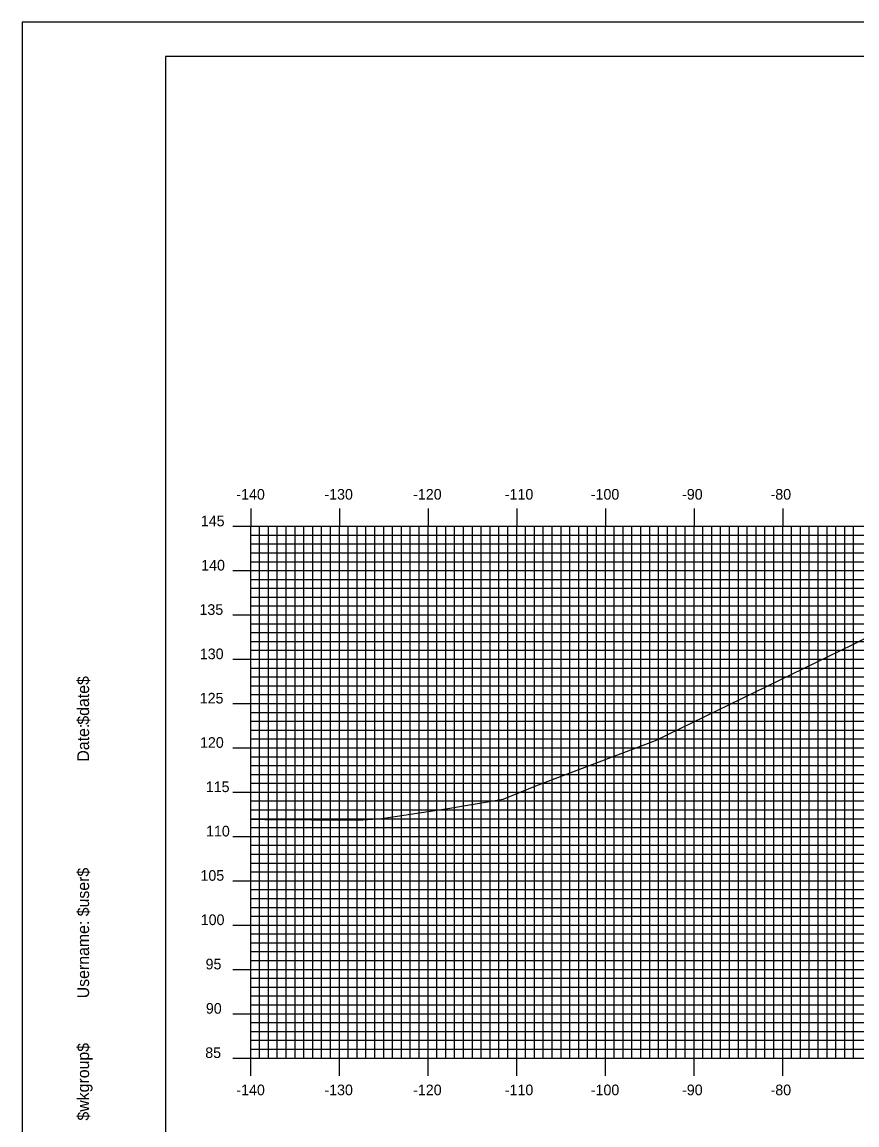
# Model space of a CAD drawing. Extents: x 859865 to 860208, y 364765 to 364985.
# Drawn here: x 859864.6 to 859958.8, y 364860.7 to 364985.2 of the extents above; entities that cross this region are included whole.
import ezdxf

# ---------------------------------------------------------------- set-up
doc = ezdxf.new("R2010")
doc.units = 0
for name, color, linetype in [('BORDER', 7, 'Continuous'), ('H_V ANNOTATION', 7, 'Continuous'), ('MAJOR', 7, 'Continuous'), ('MINOR', 7, 'Continuous'), ('PLOT BOUNDARY', 7, 'Continuous'), ('S_Roadway_Centerline', 7, 'Continuous')]:
    doc.layers.add(name, color=color, linetype=linetype)

msp = doc.modelspace()

# ---------------------------------------------------------------- linework, layer by layer
at = {"layer": 'BORDER'}
msp.add_lwpolyline([(859880.79, 364771.3), (860200.79, 364771.3), (860200.79, 364981.3), (859880.79, 364981.3)], close=True, dxfattribs=at)
at = {"layer": 'MAJOR'}
for p, q in [((859890.39, 364930.31), (859890.39, 364928.3)), ((859900.39, 364930.31), (859900.39, 364928.3)), ((859910.39, 364930.31), (859910.39, 364928.3)), ((859920.39, 364930.31), (859920.39, 364928.3)), ((859930.39, 364930.31), (859930.39, 364928.3)), ((859940.39, 364930.31), (859940.39, 364928.3)), ((859950.39, 364930.31), (859950.39, 364928.3)), ((859888.38, 364928.3), (859890.39, 364928.3)), ((859890.39, 364928.3), (860170.39, 364928.3)), ((859890.39, 364868.3), (859890.39, 364928.3)), ((859890.39, 364868.3), (859890.39, 364928.3)), ((859890.39, 364928.3), (860170.39, 364928.3)), ((859900.39, 364868.3), (859900.39, 364928.3)), ((859910.39, 364868.3), (859910.39, 364928.3)), ((859920.39, 364868.3), (859920.39, 364928.3)), ((859930.39, 364868.3), (859930.39, 364928.3)), ((859940.39, 364868.3), (859940.39, 364928.3)), ((859950.39, 364868.3), (859950.39, 364928.3)), ((859888.38, 364923.3), (859890.39, 364923.3)), ((859890.39, 364923.3), (860170.39, 364923.3)), ((859888.38, 364918.3), (859890.39, 364918.3)), ((859890.39, 364918.3), (860170.39, 364918.3)), ((859888.38, 364913.3), (859890.39, 364913.3)), ((859890.39, 364913.3), (860170.39, 364913.3)), ((859888.38, 364908.3), (859890.39, 364908.3)), ((859890.39, 364908.3), (860170.39, 364908.3)), ((859888.38, 364903.3), (859890.39, 364903.3)), ((859890.39, 364903.3), (860170.39, 364903.3)), ((859888.38, 364898.3), (859890.39, 364898.3)), ((859890.39, 364898.3), (860170.39, 364898.3)), ((859888.38, 364893.3), (859890.39, 364893.3)), ((859890.39, 364893.3), (860170.39, 364893.3)), ((859888.38, 364888.3), (859890.39, 364888.3)), ((859890.39, 364888.3), (860170.39, 364888.3)), ((859888.38, 364883.3), (859890.39, 364883.3)), ((859890.39, 364883.3), (860170.39, 364883.3)), ((859888.38, 364878.3), (859890.39, 364878.3)), ((859890.39, 364878.3), (860170.39, 364878.3)), ((859888.38, 364873.3), (859890.39, 364873.3)), ((859890.39, 364873.3), (860170.39, 364873.3)), ((859888.38, 364868.3), (859890.39, 364868.3)), ((859890.39, 364868.3), (860170.39, 364868.3)), ((859890.39, 364868.3), (860170.39, 364868.3)), ((859890.39, 364866.3), (859890.39, 364868.3)), ((859900.39, 364866.3), (859900.39, 364868.3)), ((859910.39, 364866.3), (859910.39, 364868.3)), ((859920.39, 364866.3), (859920.39, 364868.3)), ((859930.39, 364866.3), (859930.39, 364868.3)), ((859940.39, 364866.3), (859940.39, 364868.3)), ((859950.39, 364866.3), (859950.39, 364868.3))]:
    msp.add_line(p, q, dxfattribs=at)
at = {"layer": 'MINOR'}
for p, q in [((859891.39, 364868.3), (859891.39, 364928.3)), ((859892.39, 364868.3), (859892.39, 364928.3)), ((859893.39, 364868.3), (859893.39, 364928.3)), ((859894.39, 364868.3), (859894.39, 364928.3)), ((859895.39, 364868.3), (859895.39, 364928.3)), ((859896.39, 364868.3), (859896.39, 364928.3)), ((859897.39, 364868.3), (859897.39, 364928.3)), ((859898.39, 364868.3), (859898.39, 364928.3)), ((859899.39, 364868.3), (859899.39, 364928.3)), ((859901.39, 364868.3), (859901.39, 364928.3)), ((859902.39, 364868.3), (859902.39, 364928.3)), ((859903.39, 364868.3), (859903.39, 364928.3)), ((859904.39, 364868.3), (859904.39, 364928.3)), ((859905.39, 364868.3), (859905.39, 364928.3)), ((859906.39, 364868.3), (859906.39, 364928.3)), ((859907.39, 364868.3), (859907.39, 364928.3)), ((859908.39, 364868.3), (859908.39, 364928.3)), ((859909.39, 364868.3), (859909.39, 364928.3)), ((859911.39, 364868.3), (859911.39, 364928.3)), ((859912.39, 364868.3), (859912.39, 364928.3)), ((859913.39, 364868.3), (859913.39, 364928.3)), ((859914.39, 364868.3), (859914.39, 364928.3)), ((859915.39, 364868.3), (859915.39, 364928.3)), ((859916.39, 364868.3), (859916.39, 364928.3)), ((859917.39, 364868.3), (859917.39, 364928.3)), ((859918.39, 364868.3), (859918.39, 364928.3)), ((859919.39, 364868.3), (859919.39, 364928.3)), ((859921.39, 364868.3), (859921.39, 364928.3)), ((859922.39, 364868.3), (859922.39, 364928.3)), ((859923.39, 364868.3), (859923.39, 364928.3)), ((859924.39, 364868.3), (859924.39, 364928.3)), ((859925.39, 364868.3), (859925.39, 364928.3)), ((859926.39, 364868.3), (859926.39, 364928.3)), ((859927.39, 364868.3), (859927.39, 364928.3)), ((859928.39, 364868.3), (859928.39, 364928.3)), ((859929.39, 364868.3), (859929.39, 364928.3)), ((859931.39, 364868.3), (859931.39, 364928.3)), ((859932.39, 364868.3), (859932.39, 364928.3)), ((859933.39, 364868.3), (859933.39, 364928.3)), ((859934.39, 364868.3), (859934.39, 364928.3)), ((859935.39, 364868.3), (859935.39, 364928.3)), ((859936.39, 364868.3), (859936.39, 364928.3)), ((859937.39, 364868.3), (859937.39, 364928.3)), ((859938.39, 364868.3), (859938.39, 364928.3)), ((859939.39, 364868.3), (859939.39, 364928.3)), ((859941.39, 364868.3), (859941.39, 364928.3)), ((859942.39, 364868.3), (859942.39, 364928.3)), ((859943.39, 364868.3), (859943.39, 364928.3)), ((859944.39, 364868.3), (859944.39, 364928.3)), ((859945.39, 364868.3), (859945.39, 364928.3)), ((859946.39, 364868.3), (859946.39, 364928.3)), ((859947.39, 364868.3), (859947.39, 364928.3)), ((859948.39, 364868.3), (859948.39, 364928.3)), ((859949.39, 364868.3), (859949.39, 364928.3)), ((859951.39, 364868.3), (859951.39, 364928.3)), ((859952.39, 364868.3), (859952.39, 364928.3)), ((859953.39, 364868.3), (859953.39, 364928.3)), ((859954.39, 364868.3), (859954.39, 364928.3)), ((859955.39, 364868.3), (859955.39, 364928.3)), ((859956.39, 364868.3), (859956.39, 364928.3)), ((859957.39, 364868.3), (859957.39, 364928.3)), ((859958.39, 364868.3), (859958.39, 364928.3)), ((859890.39, 364927.3), (860170.39, 364927.3)), ((859890.39, 364927.3), (859892.39, 364927.3)), ((859890.39, 364926.3), (860170.39, 364926.3)), ((859890.39, 364926.3), (859892.39, 364926.3)), ((859890.39, 364925.3), (860170.39, 364925.3)), ((859890.39, 364925.3), (859892.39, 364925.3)), ((859890.39, 364924.3), (860170.39, 364924.3)), ((859890.39, 364924.3), (859892.39, 364924.3)), ((859890.39, 364922.3), (860170.39, 364922.3)), ((859890.39, 364922.3), (859892.39, 364922.3)), ((859890.39, 364921.3), (860170.39, 364921.3)), ((859890.39, 364921.3), (859892.39, 364921.3)), ((859890.39, 364920.3), (860170.39, 364920.3)), ((859890.39, 364920.3), (859892.39, 364920.3)), ((859890.39, 364919.3), (860170.39, 364919.3)), ((859890.39, 364919.3), (859892.39, 364919.3)), ((859890.39, 364917.3), (860170.39, 364917.3)), ((859890.39, 364917.3), (859892.39, 364917.3)), ((859890.39, 364916.3), (860170.39, 364916.3)), ((859890.39, 364916.3), (859892.39, 364916.3)), ((859890.39, 364915.3), (860170.39, 364915.3)), ((859890.39, 364915.3), (859892.39, 364915.3)), ((859890.39, 364914.3), (860170.39, 364914.3)), ((859890.39, 364914.3), (859892.39, 364914.3)), ((859890.39, 364912.3), (860170.39, 364912.3)), ((859890.39, 364912.3), (859892.39, 364912.3)), ((859890.39, 364911.3), (860170.39, 364911.3)), ((859890.39, 364911.3), (859892.39, 364911.3)), ((859890.39, 364910.3), (860170.39, 364910.3)), ((859890.39, 364910.3), (859892.39, 364910.3)), ((859890.39, 364909.3), (860170.39, 364909.3)), ((859890.39, 364909.3), (859892.39, 364909.3)), ((859890.39, 364907.3), (860170.39, 364907.3)), ((859890.39, 364907.3), (859892.39, 364907.3)), ((859890.39, 364906.3), (860170.39, 364906.3)), ((859890.39, 364906.3), (859892.39, 364906.3)), ((859890.39, 364905.3), (860170.39, 364905.3)), ((859890.39, 364905.3), (859892.39, 364905.3)), ((859890.39, 364904.3), (860170.39, 364904.3)), ((859890.39, 364904.3), (859892.39, 364904.3)), ((859890.39, 364902.3), (860170.39, 364902.3)), ((859890.39, 364902.3), (859892.39, 364902.3)), ((859890.39, 364901.3), (860170.39, 364901.3)), ((859890.39, 364901.3), (859892.39, 364901.3)), ((859890.39, 364900.3), (860170.39, 364900.3)), ((859890.39, 364900.3), (859892.39, 364900.3)), ((859890.39, 364899.3), (860170.39, 364899.3)), ((859890.39, 364899.3), (859892.39, 364899.3)), ((859890.39, 364897.3), (860170.39, 364897.3)), ((859890.39, 364897.3), (859892.39, 364897.3)), ((859890.39, 364896.3), (860170.39, 364896.3)), ((859890.39, 364896.3), (859892.39, 364896.3)), ((859890.39, 364895.3), (860170.39, 364895.3)), ((859890.39, 364895.3), (859892.39, 364895.3)), ((859890.39, 364894.3), (860170.39, 364894.3)), ((859890.39, 364894.3), (859892.39, 364894.3)), ((859890.39, 364892.3), (860170.39, 364892.3)), ((859890.39, 364892.3), (859892.39, 364892.3)), ((859890.39, 364891.3), (860170.39, 364891.3)), ((859890.39, 364891.3), (859892.39, 364891.3)), ((859890.39, 364890.3), (860170.39, 364890.3)), ((859890.39, 364890.3), (859892.39, 364890.3)), ((859890.39, 364889.3), (860170.39, 364889.3)), ((859890.39, 364889.3), (859892.39, 364889.3)), ((859890.39, 364887.3), (860170.39, 364887.3)), ((859890.39, 364887.3), (859892.39, 364887.3)), ((859890.39, 364886.3), (860170.39, 364886.3)), ((859890.39, 364886.3), (859892.39, 364886.3)), ((859890.39, 364885.3), (860170.39, 364885.3)), ((859890.39, 364885.3), (859892.39, 364885.3)), ((859890.39, 364884.3), (860170.39, 364884.3)), ((859890.39, 364884.3), (859892.39, 364884.3)), ((859890.39, 364882.3), (860170.39, 364882.3)), ((859890.39, 364882.3), (859892.39, 364882.3)), ((859890.39, 364881.3), (860170.39, 364881.3)), ((859890.39, 364881.3), (859892.39, 364881.3)), ((859890.39, 364880.3), (860170.39, 364880.3)), ((859890.39, 364880.3), (859892.39, 364880.3)), ((859890.39, 364879.3), (860170.39, 364879.3)), ((859890.39, 364879.3), (859892.39, 364879.3)), ((859890.39, 364877.3), (860170.39, 364877.3)), ((859890.39, 364877.3), (859892.39, 364877.3)), ((859890.39, 364876.3), (860170.39, 364876.3)), ((859890.39, 364876.3), (859892.39, 364876.3)), ((859890.39, 364875.3), (860170.39, 364875.3)), ((859890.39, 364875.3), (859892.39, 364875.3)), ((859890.39, 364874.3), (860170.39, 364874.3)), ((859890.39, 364874.3), (859892.39, 364874.3)), ((859890.39, 364872.3), (860170.39, 364872.3)), ((859890.39, 364872.3), (859892.39, 364872.3)), ((859890.39, 364871.3), (860170.39, 364871.3)), ((859890.39, 364871.3), (859892.39, 364871.3)), ((859890.39, 364870.3), (860170.39, 364870.3)), ((859890.39, 364870.3), (859892.39, 364870.3)), ((859890.39, 364869.3), (860170.39, 364869.3)), ((859890.39, 364869.3), (859892.39, 364869.3))]:
    msp.add_line(p, q, dxfattribs=at)
at = {"layer": 'PLOT BOUNDARY'}
msp.add_lwpolyline([(859864.6, 364765.18), (860204.6, 364765.18), (860204.6, 364985.18), (859864.6, 364985.18)], close=True, dxfattribs=at)
at = {"layer": 'S_Roadway_Centerline'}
msp.add_lwpolyline([(859890.39, 364895.26), (859891.97, 364895.23), (859902.52, 364895.12), (859905.19, 364895.32), (859912.41, 364896.41), (859918.87, 364897.52), (859922.54, 364899.01), (859936.06, 364904.11), (859958.29, 364914.96), (859968.57, 364920.02), (859980.94, 364920.76), (859988.01, 364921.21), (860000.55, 364921.58), (860018.51, 364922.11), (860035.53, 364922.39), (860038.79, 364922.46), (860042.21, 364920.74), (860061.3, 364911.05)], dxfattribs=at)

# ---------------------------------------------------------------- texts
at = {"layer": 'BORDER'}
for s, p in [('$date$', (859872.16, 364905.91)), ('Date:', (859872.16, 364901.74)), ('$user$', (859872.16, 364884.29)), ('Username:', (859872.16, 364875.04)), ('$wkgroup$', (859872.16, 364861.24))]:
    msp.add_text(s, height=1.339, rotation=90, dxfattribs=at).set_placement(p)
at = {"layer": 'H_V ANNOTATION'}
for s, p in [('-140', (859888.77, 364931.3)), ('-130', (859898.7, 364931.3)), ('-120', (859908.71, 364931.3)), ('-110', (859919.05, 364931.3)), ('-100', (859928.75, 364931.3)), ('-90', (859939.04, 364931.3)), ('-80', (859949.02, 364931.3)), ('145', (859884.76, 364928.3)), ('145', (859884.76, 364928.3)), ('140', (859884.8, 364923.3)), ('140', (859884.8, 364923.3)), ('135', (859884.61, 364918.3)), ('135', (859884.61, 364918.3)), ('130', (859884.65, 364913.3)), ('130', (859884.65, 364913.3)), ('125', (859884.64, 364908.3)), ('125', (859884.64, 364908.3)), ('120', (859884.67, 364903.3)), ('120', (859884.67, 364903.3)), ('115', (859885.32, 364898.3)), ('110', (859885.35, 364893.3)), ('105', (859884.72, 364888.3)), ('105', (859884.72, 364888.3)), ('100', (859884.75, 364883.3)), ('100', (859884.75, 364883.3)), ('95', (859885.3, 364878.3)), ('90', (859885.33, 364873.3)), ('85', (859885.26, 364868.3)), ('-140', (859888.77, 364864.1)), ('-130', (859898.7, 364864.1)), ('-120', (859908.71, 364864.1)), ('-110', (859919.05, 364864.1)), ('-100', (859928.75, 364864.1)), ('-90', (859939.04, 364864.1)), ('-80', (859949.02, 364864.1))]:
    msp.add_text(s, height=1.2, dxfattribs=at).set_placement(p)
at = {"layer": 'MAJOR'}
msp.add_text('-', height=0.012, dxfattribs=at).set_placement((859890.38, 364868.3))

doc.saveas('drawing.dxf')
